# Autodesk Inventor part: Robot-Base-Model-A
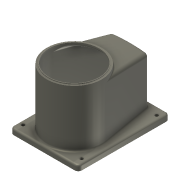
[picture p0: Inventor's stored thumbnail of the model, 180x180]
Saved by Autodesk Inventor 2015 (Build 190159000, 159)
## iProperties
Shininess: 21.0
Length Units: 11269
Angle Units: 11279
Time Units: 11290
Mass Units: 11283
Length Display Precision: 3
Angle Display Precision: 2
Created: 2001-08
Part Number: Robot-Base-Model-A
Document SubType Name: ﾓﾃﾞﾘﾝｸﾞ
Designer: Administrator
Density: 1 g/cm^3
Material: Generic
Appearance: Smooth - Ivory
Density: 0.0
Volumn: 0.0
Area: 0.0
PropertySet Name: Model Information
Control State: 0
Master: False
Checked Out: False
Author: Administrator
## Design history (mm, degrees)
node "Center-Work Plane"
fillet "Chamfer1" dims "d14" = 10
fillet "Chamfer2" dims "d15" = 5
fillet "Chamfer3" dims "d16" = 10
fillet "Chamfer4" dims "d30" = 5
shell "Shell1" dims "d34" = 2
body "Solid1"
sketch "Sketch1"
  geometry: L1 (-93, 168)-(93, 168); L2 (93, 168)-(93, -82); L3 (93, -82)-(-93, -82); L4 (-93, -82)-(-93, 168); L5 (-93, 0)-(93, 0); L6 (0, 168)-(0, -82); 2 further points
  constraints: 12 end point, 3 midpoint, 3 point on line, 2 parallel, 1 coincident, 1 horizontal, 1 perpendicular, 1 other
  dimensions: "d0" = 250 distance of L3.end L1.start; "d1" = 186 distance of L1.start L1.end; "d2" = 82 distance between parallel lines of L3 L5
extrude "Extrusion1" new body sketch "Sketch1" distance "d3" = 15; taper "d4" = 0 deg
sketch "Sketch2"
  geometry: C1 r 75 at (0, 0)
  constraints: 1 centre point
  dimensions: "d5" = 150 diameter of C1
extrude "Extrusion2" join sketch "Sketch2" distance "d6" = 155; taper "d7" = 0 deg
sketch "Sketch3"
  geometry: L1 (-93, 168)-(93, 168) reference; L2 (-50, 153)-(50, 153); L3 (0, 197.064)-(0, -91.178); L4 (50, 153)-(73.933, 12.603); L5 (-50, 153)-(-73.933, 12.603); L6 (-73.933, 12.603)-(73.933, 12.603); A1 r 75 centre (0, 0) between (73.933, 12.603) and (-73.933, 12.603) reference
  constraints: 10 end point, 2 point on circle, 2 tangent, 1 parallel, 1 perpendicular, 1 point on line
  dimensions: "d8" = 50 distance from line of L2.start L3; "d9" = 50 distance from line of L2.end L3; "d10" = 15 distance between parallel lines of L2 L1
extrude "Extrusion3" join sketch "Sketch3" distance "d11" = 145; taper "d12" = 0 deg
feature "FaceDraft" dims angle "d13" = 10 deg
sketch "Sketch4"
  geometry: L1 (-93, -72)-(-93, 158) reference; L2 (-80, 145)-(80, 145); L3 (-80, 145)-(-80, -173.228); L4 (80, 145)-(80, -173.228); L5 (-80, -60)-(80, -60); L6 (0, 145)-(0, -60); 5 further points
  constraints: 10 end point, 4 coincident, 3 point on line, 2 midpoint, 2 parallel, 2 perpendicular, 1 other
  dimensions: "d19" = 160 distance between parallel lines of L4 L3; "d21" = 205 distance between parallel lines of L5 L2; "d22" = 60 distance from line of L5 point (0, 0)
hole "Hole1" sketch "Sketch4" diameter "d23" = 9; stored, may be unused: countersink angle "d27" = 82 deg, drill point angle "d29" = 118 deg; dims "d24" = 6, "d25" = 4, "d26" = 2, "d28" = 8
sketch "Sketch5"
  geometry: C1 r 75 at (0, 0) reference; C2 r 70 at (0, 0)
  constraints: 1 centre point
  dimensions: "d31" = 5 radial gap between concentric circles of C1 C2
extrude "Extrusion4" join sketch "Sketch5" distance "d32" = 2; taper "d33" = 0 deg
